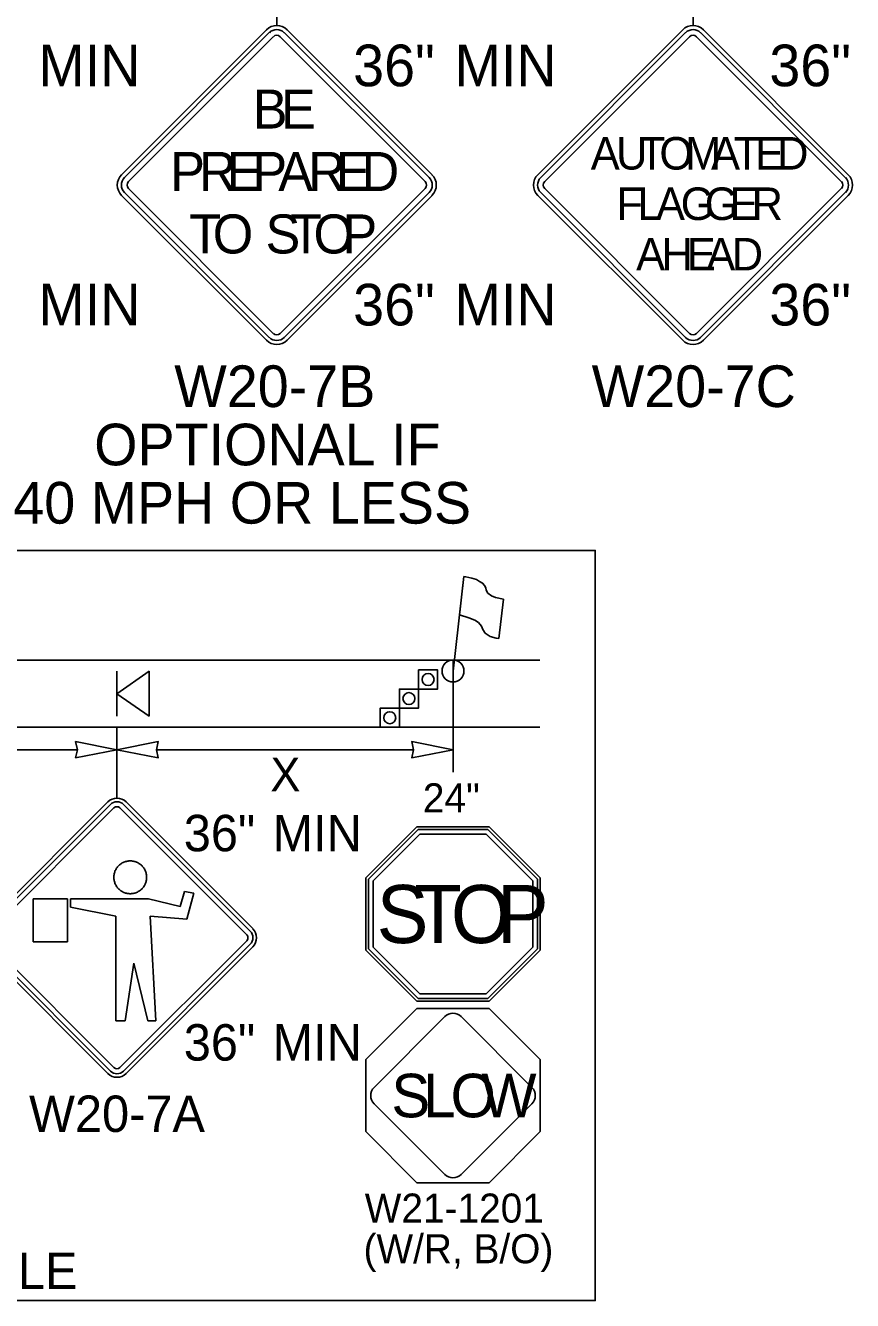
# Model space of a CAD drawing. Extents: x 99999.1 to 100095.7, y 99995 to 100010.7.
# Drawn here: x 100042.194 to 100043.783, y 100003.042 to 100005.492 of the extents above; entities that cross this region are included whole.
import ezdxf

# ---------------------------------------------------------------- set-up
doc = ezdxf.new("R2010")
doc.units = 0
for name, color, linetype in [('RD_ED_ShoulderPavedEdge', 7, 'Continuous'), ('RD_MK_LineEdgeWhite', 7, 'Continuous'), ('TR_SN_ConstructionSigns', 7, 'Continuous'), ('TR_WZ_FlaggingStation', 7, 'Continuous'), ('TR_WZ_PortableSignMountBlk-Org', 7, 'Continuous'), ('TR_WZ_TrafficCone', 7, 'Continuous'), ('TR_WZ_WorkZoneDetails', 7, 'Continuous'), ('TR_WZ_WorkZoneTextCurrent', 7, 'Continuous')]:
    doc.layers.add(name, color=color, linetype=linetype)

msp = doc.modelspace()

# ---------------------------------------------------------------- linework, layer by layer
at = {"layer": 'RD_ED_ShoulderPavedEdge'}
msp.add_line((100040.2089, 100004.1438), (100043.1825, 100004.1438), dxfattribs=at)
at = {"layer": 'RD_MK_LineEdgeWhite'}
msp.add_line((100040.2089, 100004.273), (100043.1825, 100004.273), dxfattribs=at)
at = {"layer": 'TR_SN_ConstructionSigns'}
for p, q in [((100042.6568, 100005.4841), (100042.3783, 100005.2057)), ((100042.6623, 100005.4786), (100042.3839, 100005.2001)), ((100042.3916, 100005.1924), (100042.67, 100005.4708)), ((100042.6833, 100005.4708), (100042.9617, 100005.1924)), ((100042.9694, 100005.2001), (100042.691, 100005.4786)), ((100042.975, 100005.2057), (100042.6965, 100005.4841)), ((100043.4568, 100005.4841), (100043.1783, 100005.2057)), ((100043.4623, 100005.4786), (100043.1839, 100005.2001)), ((100043.1916, 100005.1924), (100043.47, 100005.4708)), ((100043.4833, 100005.4708), (100043.7617, 100005.1924)), ((100043.7694, 100005.2001), (100043.491, 100005.4786)), ((100043.775, 100005.2057), (100043.4965, 100005.4841)), ((100042.3839, 100005.1714), (100042.6623, 100004.893)), ((100042.67, 100004.9007), (100042.3916, 100005.1792)), ((100042.9617, 100005.1792), (100042.6833, 100004.9007)), ((100042.691, 100004.893), (100042.9694, 100005.1714)), ((100043.1839, 100005.1714), (100043.4623, 100004.893)), ((100043.47, 100004.9007), (100043.1916, 100005.1792)), ((100043.7617, 100005.1792), (100043.4833, 100004.9007)), ((100043.491, 100004.893), (100043.7694, 100005.1714)), ((100042.3783, 100005.1659), (100042.6568, 100004.8875)), ((100042.6965, 100004.8875), (100042.975, 100005.1659)), ((100043.1783, 100005.1659), (100043.4568, 100004.8875)), ((100043.4965, 100004.8875), (100043.775, 100005.1659)), ((100042.3521, 100004.0005), (100042.1084, 100003.7569)), ((100042.3569, 100003.9957), (100042.1133, 100003.752)), ((100042.6257, 100003.752), (100042.382, 100003.9957)), ((100042.6305, 100003.7569), (100042.3869, 100004.0005)), ((100042.12, 100003.7453), (100042.3637, 100003.9889)), ((100042.3753, 100003.9889), (100042.6189, 100003.7453)), ((100042.946, 100003.9525), (100042.8479, 100003.8544)), ((100042.9482, 100003.9472), (100042.8531, 100003.8522)), ((100043.0847, 100003.9525), (100042.946, 100003.9525)), ((100043.0825, 100003.9472), (100042.9482, 100003.9472)), ((100043.1775, 100003.8522), (100043.0825, 100003.9472)), ((100043.1828, 100003.8544), (100043.0847, 100003.9525)), ((100042.8619, 100003.8486), (100042.9518, 100003.9385)), ((100042.9518, 100003.9385), (100043.0789, 100003.9385)), ((100043.0789, 100003.9385), (100043.1688, 100003.8486)), ((100042.367, 100003.8702), (100042.3663, 100003.8686)), ((100042.3678, 100003.8716), (100042.367, 100003.8702)), ((100042.3688, 100003.8731), (100042.3678, 100003.8716)), ((100042.3697, 100003.8744), (100042.3688, 100003.8731)), ((100042.3707, 100003.8757), (100042.3697, 100003.8744)), ((100042.3718, 100003.877), (100042.3707, 100003.8757)), ((100042.373, 100003.8782), (100042.3718, 100003.877)), ((100042.3742, 100003.8794), (100042.373, 100003.8782)), ((100042.3755, 100003.8804), (100042.3742, 100003.8794)), ((100042.3769, 100003.8814), (100042.3755, 100003.8804)), ((100042.3783, 100003.8823), (100042.3769, 100003.8814)), ((100042.3797, 100003.8832), (100042.3783, 100003.8823)), ((100042.3812, 100003.884), (100042.3797, 100003.8832)), ((100042.3827, 100003.8847), (100042.3812, 100003.884)), ((100042.3843, 100003.8853), (100042.3827, 100003.8847)), ((100042.3859, 100003.8858), (100042.3843, 100003.8853)), ((100042.3875, 100003.8862), (100042.3859, 100003.8858)), ((100042.3892, 100003.8866), (100042.3875, 100003.8862)), ((100042.3908, 100003.8869), (100042.3892, 100003.8866)), ((100042.3925, 100003.887), (100042.3908, 100003.8869)), ((100042.3942, 100003.8871), (100042.3925, 100003.887)), ((100042.3959, 100003.8871), (100042.3942, 100003.8871)), ((100042.3975, 100003.887), (100042.3959, 100003.8871)), ((100042.3992, 100003.8869), (100042.3975, 100003.887)), ((100042.4008, 100003.8866), (100042.3992, 100003.8869)), ((100042.4025, 100003.8862), (100042.4008, 100003.8866)), ((100042.4041, 100003.8858), (100042.4025, 100003.8862)), ((100042.4057, 100003.8853), (100042.4041, 100003.8858)), ((100042.4072, 100003.8847), (100042.4057, 100003.8853)), ((100042.4088, 100003.884), (100042.4072, 100003.8847)), ((100042.4103, 100003.8832), (100042.4088, 100003.884)), ((100042.4117, 100003.8823), (100042.4103, 100003.8832)), ((100042.4131, 100003.8814), (100042.4117, 100003.8823)), ((100042.4145, 100003.8804), (100042.4131, 100003.8814)), ((100042.4157, 100003.8794), (100042.4145, 100003.8804)), ((100042.417, 100003.8782), (100042.4157, 100003.8794)), ((100042.4181, 100003.877), (100042.417, 100003.8782)), ((100042.4192, 100003.8757), (100042.4181, 100003.877)), ((100042.4203, 100003.8744), (100042.4192, 100003.8757)), ((100042.4213, 100003.8731), (100042.4203, 100003.8744)), ((100042.4221, 100003.8716), (100042.4213, 100003.8731)), ((100042.423, 100003.8702), (100042.4221, 100003.8716)), ((100042.4237, 100003.8686), (100042.423, 100003.8702)), ((100042.3637, 100003.8589), (100042.3635, 100003.8573)), ((100042.3635, 100003.8573), (100042.3635, 100003.8556)), ((100042.3635, 100003.8556), (100042.3635, 100003.854)), ((100042.3635, 100003.854), (100042.3637, 100003.8523)), ((100042.3639, 100003.8606), (100042.3637, 100003.8589)), ((100042.3637, 100003.8523), (100042.3639, 100003.8506)), ((100042.3642, 100003.8623), (100042.3639, 100003.8606)), ((100042.3639, 100003.8506), (100042.3642, 100003.849)), ((100042.3646, 100003.8639), (100042.3642, 100003.8623)), ((100042.3642, 100003.849), (100042.3646, 100003.8473)), ((100042.3651, 100003.8655), (100042.3646, 100003.8639)), ((100042.3646, 100003.8473), (100042.3651, 100003.8457)), ((100042.3656, 100003.8671), (100042.3651, 100003.8655)), ((100042.3651, 100003.8457), (100042.3656, 100003.8442)), ((100042.3663, 100003.8686), (100042.3656, 100003.8671)), ((100042.4243, 100003.8671), (100042.4237, 100003.8686)), ((100042.4249, 100003.8655), (100042.4243, 100003.8671)), ((100042.4243, 100003.8442), (100042.4249, 100003.8457)), ((100042.4254, 100003.8639), (100042.4249, 100003.8655)), ((100042.4249, 100003.8457), (100042.4254, 100003.8473)), ((100042.4258, 100003.8623), (100042.4254, 100003.8639)), ((100042.4254, 100003.8473), (100042.4258, 100003.849)), ((100042.4261, 100003.8606), (100042.4258, 100003.8623)), ((100042.4258, 100003.849), (100042.4261, 100003.8506)), ((100042.4264, 100003.8589), (100042.4261, 100003.8606)), ((100042.4261, 100003.8506), (100042.4264, 100003.8523)), ((100042.4265, 100003.8573), (100042.4264, 100003.8589)), ((100042.4264, 100003.8523), (100042.4265, 100003.854)), ((100042.4265, 100003.8556), (100042.4265, 100003.8573)), ((100042.4265, 100003.854), (100042.4265, 100003.8556)), ((100042.8479, 100003.8544), (100042.8479, 100003.7157)), ((100042.8531, 100003.8522), (100042.8531, 100003.7179)), ((100042.8619, 100003.7215), (100042.8619, 100003.8486)), ((100043.1688, 100003.8486), (100043.1688, 100003.7215)), ((100043.1775, 100003.7179), (100043.1775, 100003.8522)), ((100043.1828, 100003.7157), (100043.1828, 100003.8544)), ((100042.3656, 100003.8442), (100042.3663, 100003.8426)), ((100042.3663, 100003.8426), (100042.367, 100003.8411)), ((100042.367, 100003.8411), (100042.3678, 100003.8396)), ((100042.3678, 100003.8396), (100042.3688, 100003.8382)), ((100042.3688, 100003.8382), (100042.3697, 100003.8368)), ((100042.3697, 100003.8368), (100042.3707, 100003.8355)), ((100042.3707, 100003.8355), (100042.3718, 100003.8343)), ((100042.3718, 100003.8343), (100042.373, 100003.833)), ((100042.373, 100003.833), (100042.3742, 100003.8319)), ((100042.3742, 100003.8319), (100042.3755, 100003.8309)), ((100042.3755, 100003.8309), (100042.3769, 100003.8298)), ((100042.3769, 100003.8298), (100042.3783, 100003.8289)), ((100042.3783, 100003.8289), (100042.3797, 100003.8281)), ((100042.3797, 100003.8281), (100042.3812, 100003.8273)), ((100042.3812, 100003.8273), (100042.3827, 100003.8266)), ((100042.3827, 100003.8266), (100042.3843, 100003.826)), ((100042.3843, 100003.826), (100042.3859, 100003.8254)), ((100042.3859, 100003.8254), (100042.3875, 100003.825)), ((100042.3875, 100003.825), (100042.3892, 100003.8247)), ((100042.3892, 100003.8247), (100042.3908, 100003.8244)), ((100042.3908, 100003.8244), (100042.3925, 100003.8242)), ((100042.3925, 100003.8242), (100042.3942, 100003.8241)), ((100042.3942, 100003.8241), (100042.3959, 100003.8241)), ((100042.3959, 100003.8241), (100042.3975, 100003.8242)), ((100042.3975, 100003.8242), (100042.3992, 100003.8244)), ((100042.3992, 100003.8244), (100042.4008, 100003.8247)), ((100042.4008, 100003.8247), (100042.4025, 100003.825)), ((100042.4025, 100003.825), (100042.4041, 100003.8254)), ((100042.4041, 100003.8254), (100042.4057, 100003.826)), ((100042.4057, 100003.826), (100042.4072, 100003.8266)), ((100042.4072, 100003.8266), (100042.4088, 100003.8273)), ((100042.4088, 100003.8273), (100042.4103, 100003.8281)), ((100042.4103, 100003.8281), (100042.4117, 100003.8289)), ((100042.4117, 100003.8289), (100042.4131, 100003.8298)), ((100042.4131, 100003.8298), (100042.4145, 100003.8309)), ((100042.4145, 100003.8309), (100042.4157, 100003.8319)), ((100042.4157, 100003.8319), (100042.417, 100003.833)), ((100042.417, 100003.833), (100042.4181, 100003.8343)), ((100042.4181, 100003.8343), (100042.4192, 100003.8355)), ((100042.4192, 100003.8355), (100042.4203, 100003.8368)), ((100042.4203, 100003.8368), (100042.4213, 100003.8382)), ((100042.4213, 100003.8382), (100042.4221, 100003.8396)), ((100042.4221, 100003.8396), (100042.423, 100003.8411)), ((100042.423, 100003.8411), (100042.4237, 100003.8426)), ((100042.4237, 100003.8426), (100042.4243, 100003.8442)), ((100042.4996, 100003.828), (100042.4911, 100003.7992)), ((100042.517, 100003.8248), (100042.4996, 100003.828)), ((100042.5039, 100003.7751), (100042.517, 100003.8248)), ((100042.2083, 100003.8142), (100042.2083, 100003.7313)), ((100042.2742, 100003.8142), (100042.2083, 100003.8142)), ((100042.2742, 100003.7313), (100042.2742, 100003.8142)), ((100042.4302, 100003.8142), (100042.2803, 100003.8142)), ((100042.2803, 100003.8142), (100042.2803, 100003.7984)), ((100042.2803, 100003.7984), (100042.3673, 100003.7811)), ((100042.4911, 100003.7992), (100042.4302, 100003.8142)), ((100042.3673, 100003.7811), (100042.3673, 100003.5795)), ((100042.4445, 100003.5795), (100042.433, 100003.7811)), ((100042.433, 100003.7811), (100042.5039, 100003.7751)), ((100042.1133, 100003.7269), (100042.3569, 100003.4833)), ((100042.3637, 100003.4901), (100042.12, 100003.7337)), ((100042.2083, 100003.7313), (100042.2742, 100003.7313)), ((100042.6189, 100003.7337), (100042.3753, 100003.4901)), ((100042.382, 100003.4833), (100042.6257, 100003.7269)), ((100042.1084, 100003.7221), (100042.3521, 100003.4785)), ((100042.3869, 100003.4785), (100042.6305, 100003.7221)), ((100042.8479, 100003.7157), (100042.946, 100003.6176)), ((100042.8531, 100003.7179), (100042.9482, 100003.6229)), ((100042.9518, 100003.6316), (100042.8619, 100003.7215)), ((100043.1688, 100003.7215), (100043.0789, 100003.6316)), ((100043.0825, 100003.6229), (100043.1775, 100003.7179)), ((100043.0847, 100003.6176), (100043.1828, 100003.7157)), ((100042.385, 100003.5795), (100042.4022, 100003.6904)), ((100042.4022, 100003.6904), (100042.4287, 100003.5795)), ((100043.0789, 100003.6316), (100042.9518, 100003.6316)), ((100042.946, 100003.6176), (100043.0847, 100003.6176)), ((100042.9482, 100003.6229), (100043.0825, 100003.6229)), ((100042.3673, 100003.5795), (100042.385, 100003.5795)), ((100042.4287, 100003.5795), (100042.4445, 100003.5795)), ((100042.9996, 100003.5879), (100042.8637, 100003.452)), ((100043.167, 100003.452), (100043.0311, 100003.5879)), ((100042.8637, 100003.4205), (100042.9996, 100003.2846)), ((100043.0311, 100003.2846), (100043.167, 100003.4205))]:
    msp.add_line(p, q, dxfattribs=at)
msp.add_lwpolyline([(100043.1828, 100003.5056), (100043.1828, 100003.3669), (100043.0847, 100003.2688), (100042.946, 100003.2688), (100042.8479, 100003.3669), (100042.8479, 100003.5056), (100042.946, 100003.6037), (100043.0847, 100003.6037)], close=True, dxfattribs=at)
for centre, radius, start, end in [((100042.6767, 100005.4642), 0.0281, 45, 135), ((100043.4767, 100005.4642), 0.0281, 45, 135), ((100042.6767, 100005.4642), 0.0203, 45, 135), ((100042.6767, 100005.4642), 0.00937, 45, 135), ((100043.4767, 100005.4642), 0.0203, 45, 135), ((100043.4767, 100005.4642), 0.00937, 45, 135), ((100042.3982, 100005.1858), 0.0281, 135, 225), ((100042.3982, 100005.1858), 0.0203, 135, 225), ((100042.9551, 100005.1858), 0.0203, 315, 45), ((100042.9551, 100005.1858), 0.0281, 315, 45), ((100043.1982, 100005.1858), 0.0281, 135, 225), ((100043.1982, 100005.1858), 0.0203, 135, 225), ((100043.7551, 100005.1858), 0.0203, 315, 45), ((100043.7551, 100005.1858), 0.0281, 315, 45), ((100042.3982, 100005.1858), 0.00937, 135, 225), ((100042.9551, 100005.1858), 0.00937, 315, 45), ((100043.1982, 100005.1858), 0.00937, 135, 225), ((100043.7551, 100005.1858), 0.00937, 315, 45), ((100042.6767, 100004.9074), 0.00937, 225, 315), ((100043.4767, 100004.9074), 0.00937, 225, 315), ((100042.6767, 100004.9074), 0.0281, 225, 315), ((100042.6767, 100004.9074), 0.0203, 225, 315), ((100043.4767, 100004.9074), 0.0281, 225, 315), ((100043.4767, 100004.9074), 0.0203, 225, 315), ((100042.3695, 100003.9831), 0.0246, 45, 135), ((100042.3695, 100003.9831), 0.0178, 45, 135), ((100042.3695, 100003.9831), 0.0082, 45, 135), ((100042.6131, 100003.7395), 0.0178, 315, 45), ((100042.6131, 100003.7395), 0.0246, 315, 45), ((100042.6131, 100003.7395), 0.0082, 315, 45), ((100043.0153, 100003.5721), 0.0223, 45, 135), ((100042.3695, 100003.4959), 0.0246, 225, 315), ((100042.3695, 100003.4959), 0.0178, 225, 315), ((100042.3695, 100003.4959), 0.0082, 225, 315), ((100042.8795, 100003.4362), 0.0223, 135, 225), ((100043.1512, 100003.4362), 0.0223, 315, 45), ((100043.0153, 100003.3004), 0.0223, 225, 315)]:
    msp.add_arc(centre, radius, start, end, dxfattribs=at)
at = {"layer": 'TR_WZ_FlaggingStation'}
for p, q in [((100043.0154, 100004.252), (100043.0361, 100004.4335)), ((100043.0277, 100004.3598), (100043.0361, 100004.4337)), ((100043.1123, 100004.3899), (100043.1037, 100004.3142)), ((100043.0277, 100004.3598), (100043.0277, 100004.3598))]:
    msp.add_line(p, q, dxfattribs=at)
for points in [[(100043.0361, 100004.4337), (100043.0398, 100004.4329), (100043.0514, 100004.4307), (100043.0603, 100004.428), (100043.0665, 100004.424), (100043.0721, 100004.421), (100043.0757, 100004.4166), (100043.0785, 100004.4115), (100043.0788, 100004.4075), (100043.0823, 100004.4016), (100043.0892, 100004.3967), (100043.0973, 100004.3934), (100043.1123, 100004.3899)], [(100043.1037, 100004.3142), (100043.0985, 100004.3151), (100043.087, 100004.3181), (100043.0769, 100004.3249), (100043.0727, 100004.3317), (100043.0702, 100004.3384), (100043.0643, 100004.3454), (100043.0572, 100004.3494), (100043.046, 100004.354), (100043.0277, 100004.3598)]]:
    msp.add_lwpolyline(points, dxfattribs=at)
msp.add_circle((100043.0154, 100004.252), 0.021, dxfattribs=at)
at = {"layer": 'TR_WZ_PortableSignMountBlk-Org'}
msp.add_line((100042.3695, 100004.1654), (100042.3695, 100004.2515), dxfattribs=at)
msp.add_lwpolyline([(100042.3695, 100004.2084), (100042.4313, 100004.2515), (100042.4313, 100004.1654)], close=True, dxfattribs=at)
at = {"layer": 'TR_WZ_TrafficCone'}
for points in [[(100042.9491, 100004.2541), (100042.9858, 100004.2541), (100042.9858, 100004.2173), (100042.9491, 100004.2173), (100042.9491, 100004.2541)], [(100042.9491, 100004.2173), (100042.9858, 100004.2173), (100042.9858, 100004.2541), (100042.9491, 100004.2541), (100042.9491, 100004.2173)], [(100042.9123, 100004.2173), (100042.9491, 100004.2173), (100042.9491, 100004.1806), (100042.9123, 100004.1806), (100042.9123, 100004.2173)], [(100042.9123, 100004.1806), (100042.9491, 100004.1806), (100042.9491, 100004.2173), (100042.9123, 100004.2173), (100042.9123, 100004.1806)], [(100042.8756, 100004.1806), (100042.9123, 100004.1806), (100042.9123, 100004.1438), (100042.8756, 100004.1438), (100042.8756, 100004.1806)], [(100042.8756, 100004.1438), (100042.9123, 100004.1438), (100042.9123, 100004.1806), (100042.8756, 100004.1806), (100042.8756, 100004.1438)]]:
    msp.add_lwpolyline(points, dxfattribs=at)
for centre in [(100042.9674, 100004.2357), (100042.9307, 100004.199), (100042.8939, 100004.1622)]:
    msp.add_circle(centre, 0.0115, dxfattribs=at)
at = {"layer": 'TR_WZ_WorkZoneDetails'}
for p, q in [((100042.6767, 100005.7323), (100042.6767, 100005.4923)), ((100043.4767, 100005.7323), (100043.4767, 100005.4923)), ((100043.0154, 100004.273), (100043.0154, 100004.0577)), ((100042.3695, 100004.1438), (100042.3695, 100004.0077)), ((100042.2938, 100004.1008), (100041.7992, 100004.1008)), ((100042.9397, 100004.1008), (100042.4452, 100004.1008))]:
    msp.add_line(p, q, dxfattribs=at)
for points in [[(100042.3695, 100004.1008), (100042.2901, 100004.1163), (100042.2938, 100004.1008), (100042.2901, 100004.0852)], [(100042.3695, 100004.1008), (100042.4488, 100004.1163), (100042.4452, 100004.1008), (100042.4488, 100004.0852)], [(100043.0154, 100004.1008), (100042.9361, 100004.1163), (100042.9397, 100004.1008), (100042.9361, 100004.0852)]]:
    msp.add_lwpolyline(points, close=True, dxfattribs=at)
at = {"layer": 'TR_WZ_WorkZoneTextCurrent'}
msp.add_lwpolyline([(100040.1, 100004.4837), (100043.2886, 100004.4837), (100043.2886, 100003.0424), (100040.1, 100003.0424)], close=True, dxfattribs=at)

# ---------------------------------------------------------------- texts
at = {"layer": 'TR_SN_ConstructionSigns'}
for s, height, p in [('MIN', 0.08, (100042.2184, 100005.3756)), ('36"', 0.08, (100042.8234, 100005.3756)), ('MIN', 0.08, (100043.0184, 100005.3756)), ('36"', 0.08, (100043.6234, 100005.3756)), ('36"', 0.08, (100042.8234, 100004.916)), ('36"', 0.08, (100043.6234, 100004.916)), ('MIN', 0.08, (100042.2184, 100004.916)), ('MIN', 0.08, (100043.0184, 100004.916)), ('W20-7B', 0.08, (100042.4796, 100004.7592)), ('W20-7C', 0.08, (100043.2819, 100004.7592)), ('OPTIONAL IF', 0.08, (100042.3257, 100004.6472)), ('40 MPH OR LESS', 0.08, (100042.1702, 100004.5352)), ('36"', 0.07, (100042.4979, 100003.9056)), ('MIN', 0.07, (100042.6685, 100003.9056)), ('36"', 0.07, (100042.4979, 100003.5034)), ('MIN', 0.07, (100042.6685, 100003.5034)), ('W20-7A', 0.07, (100042.2004, 100003.3663)), ('W21-1201', 0.05581, (100042.8457, 100003.1921)), ('(W/R, B/O)', 0.05581, (100042.8434, 100003.114))]:
    msp.add_text(s, height=height, rotation=360, dxfattribs=at).set_placement(p)
for s, height, p in [('B', 0.075, (100042.6304, 100005.2943)), ('E', 0.075, (100042.6847, 100005.2943)), ('A', 0.0625, (100043.2801, 100005.2155)), ('U', 0.0625, (100043.3288, 100005.2155)), ('T', 0.0625, (100043.3726, 100005.2155)), ('O', 0.0625, (100043.412, 100005.2155)), ('M', 0.0625, (100043.4613, 100005.2155)), ('A', 0.0625, (100043.5113, 100005.2155)), ('T', 0.0625, (100043.5551, 100005.2155)), ('E', 0.0625, (100043.5957, 100005.2155)), ('D', 0.0625, (100043.6382, 100005.2155)), ('P', 0.075, (100042.4718, 100005.1743)), ('R', 0.075, (100042.527, 100005.1743)), ('E', 0.075, (100042.5802, 100005.1743)), ('P', 0.075, (100042.6297, 100005.1743)), ('A', 0.075, (100042.6796, 100005.1743)), ('R', 0.075, (100042.7368, 100005.1743)), ('E', 0.075, (100042.7901, 100005.1743)), ('D', 0.075, (100042.8396, 100005.1743)), ('F', 0.0625, (100043.3292, 100005.1186)), ('L', 0.0625, (100043.3698, 100005.1186)), ('A', 0.0625, (100043.4054, 100005.1186)), ('G', 0.0625, (100043.4529, 100005.1186)), ('G', 0.0625, (100043.4992, 100005.1186)), ('E', 0.0625, (100043.5467, 100005.1186)), ('R', 0.0625, (100043.5892, 100005.1186)), ('T', 0.075, (100042.5084, 100005.0543)), ('O', 0.075, (100042.5535, 100005.0543)), ('S', 0.075, (100042.655, 100005.0543)), ('T', 0.075, (100042.7021, 100005.0543)), ('O', 0.075, (100042.7472, 100005.0543)), ('P', 0.075, (100042.8029, 100005.0543)), ('A', 0.0625, (100043.3673, 100005.0217)), ('H', 0.0625, (100043.416, 100005.0217)), ('E', 0.0625, (100043.4648, 100005.0217)), ('A', 0.0625, (100043.5023, 100005.0217)), ('D', 0.0625, (100043.551, 100005.0217)), ('24"', 0.05581, (100042.9574, 100003.9804)), ('S', 0.1116, (100042.8686, 100003.7292)), ('T', 0.1116, (100042.9411, 100003.7292)), ('O', 0.1116, (100043.0114, 100003.7292)), ('P', 0.1116, (100043.0996, 100003.7292)), ('S', 0.0837, (100042.8969, 100003.3944)), ('L', 0.0837, (100042.958, 100003.3944)), ('O', 0.0837, (100043.0107, 100003.3944)), ('W', 0.0837, (100043.0702, 100003.3944))]:
    msp.add_text(s, height=height, dxfattribs=at).set_placement(p)
at = {"layer": 'TR_WZ_WorkZoneTextCurrent'}
for s, height, p in [('X', 0.0646, (100042.6644, 100004.0211)), ('UPDATE SIGNAGE & USE STOP/SLOW PADDLE', 0.07, (100040.1713, 100003.0644))]:
    msp.add_text(s, height=height, dxfattribs=at).set_placement(p)

doc.saveas('drawing.dxf')
